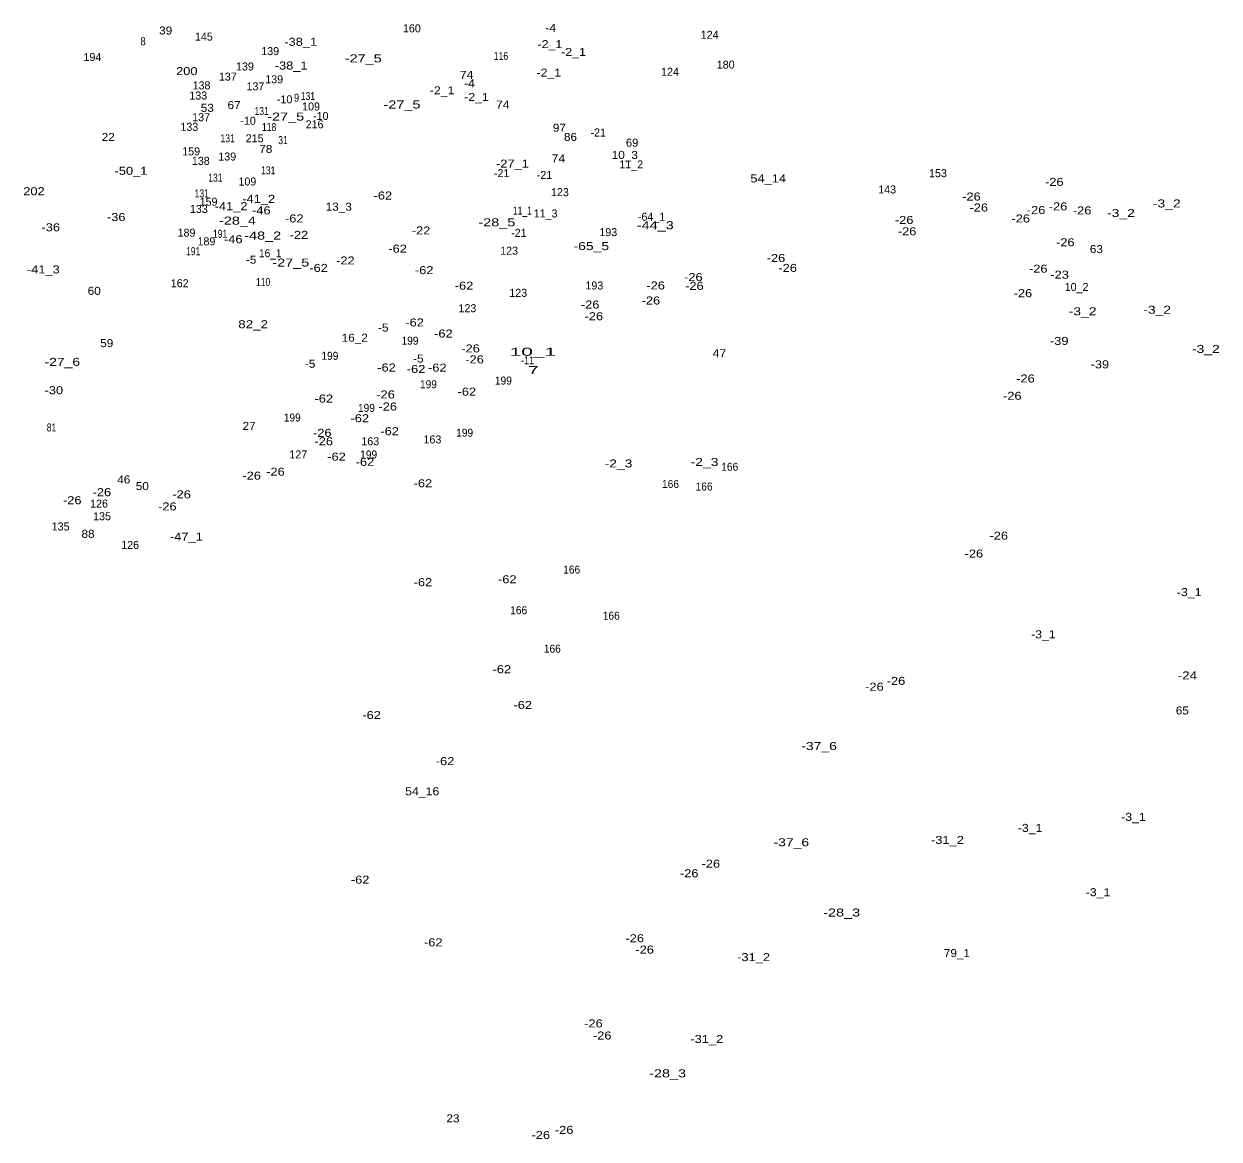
# Model space of a CAD drawing. Extents: x -660405 to -657848, y -988475 to -986360.
# Drawn here: x -658944 to -658347, y -987921 to -987364 of the extents above; entities that cross this region are included whole.
import ezdxf
from ezdxf.enums import TextEntityAlignment as Align

# ---------------------------------------------------------------- set-up
doc = ezdxf.new("R2010")
doc.units = 0
doc.header["$LTSCALE"] = 1.6
doc.layers.add('24', color=7, linetype='Continuous')

msp = doc.modelspace()

# ---------------------------------------------------------------- texts
at = {"layer": '24'}
for s, p in [('160', (-658750.03, -987368.03)), ('145', (-658853.98, -987372.15)), ('124', (-658601.199, -987371.25)), ('139', (-658820.831, -987379.41)), ('194', (-658909.69, -987382.36)), ('180', (-658593.16, -987386.17)), ('137', (-658842.01, -987392.14)), ('139', (-658833.451, -987387.08)), ('124', (-658621.02, -987389.73)), ('138', (-658855.16, -987396.55)), ('137', (-658828.211, -987396.99)), ('139', (-658818.821, -987393.49)), ('133', (-658856.77, -987401.59)), ('-10', (-658813.62, -987403.5)), ('109', (-658800.41, -987407.06)), ('137', (-658855.351, -987412.44)), ('-10', (-658831.88, -987414.2)), ('216', (-658798.64, -987415.96)), ('-10', (-658795.541, -987411.8)), ('133', (-658861.24, -987417.23)), ('-21', (-658656.88, -987420.07)), ('215', (-658828.62, -987422.97)), ('159', (-658860.331, -987429.49)), ('139', (-658842.311, -987432.06)), ('138', (-658855.53, -987434.22)), ('11_2', (-658640.37, -987435.98)), ('109', (-658832.221, -987444.54)), ('-21', (-658705.14, -987440.37)), ('-21', (-658683.75, -987441.28)), ('153', (-658487.079, -987440.38)), ('123', (-658676.02, -987449.86)), ('143', (-658512.49, -987448.53)), ('159', (-658851.64, -987454.63)), ('133', (-658856.49, -987458.27)), ('11_3', (-658683.19, -987460.49)), ('-64_1', (-658630.216, -987462.15)), ('193', (-658651.851, -987469.83)), ('189', (-658862.65, -987470.11)), ('189', (-658852.691, -987474.45)), ('-21', (-658696.551, -987470.18)), ('123', (-658701.429, -987479.12)), ('162', (-658866.061, -987495.35)), ('193', (-658658.821, -987496.48)), ('10_2', (-658417.803, -987497.19)), ('123', (-658696.86, -987500.15)), ('123', (-658722.27, -987507.83)), ('163', (-658770.831, -987574.3)), ('163', (-658739.76, -987573.38)), ('127', (-658806.77, -987580.86)), ('126', (-658906.37, -987605.41)), ('135', (-658904.86, -987611.74)), ('135', (-658925.559, -987616.86)), ('126', (-658890.831, -987626.07))]:
    msp.add_text(s, height=4, dxfattribs=at).set_placement(p, align=Align.CENTER)
for s, width, p in [('-4', 1.15, (-658680.64, -987367.83)), ('39', 1.1, (-658873.07, -987369.12)), ('8', 0.9, (-658884.37, -987374.5)), ('-38_1', 1.2, (-658805.579, -987374.77)), ('-2_1', 1.15, (-658681.03, -987375.94)), ('-2_1', 1.15, (-658669.22, -987379.82)), ('-27_5', 1.35, (-658774.34, -987383.04)), ('116', 0.8, (-658705.5, -987381.85)), ('200', 1.2, (-658862.51, -987389.42)), ('-38_1', 1.2, (-658810.34, -987386.61)), ('74', 1.15, (-658722.67, -987391.28)), ('-2_1', 1.15, (-658681.579, -987390.15)), ('-4', 1.15, (-658721.22, -987395.51)), ('9', 0.85, (-658807.64, -987402.7)), ('131', 0.8, (-658801.97, -987401.85)), ('-2_1', 1.15, (-658734.9, -987399.01)), ('-2_1', 1.15, (-658717.74, -987402.33)), ('53', 1.1, (-658852.28, -987407.74)), ('67', 1.1, (-658838.88, -987406.38)), ('131', 0.8, (-658825.09, -987409.34)), ('-27_5', 1.35, (-658754.96, -987406.08)), ('74', 1.15, (-658704.57, -987406.09)), ('-27_5', 1.35, (-658813.09, -987412.12)), ('118', 0.8, (-658821.37, -987417.32)), ('97', 1.1, (-658676.29, -987417.67)), ('22', 1.1, (-658901.77, -987422.32)), ('131', 0.8, (-658842.09, -987422.97)), ('31', 0.8, (-658814.419, -987423.86)), ('86', 1.1, (-658670.76, -987422.28)), ('69', 1.05, (-658639.95, -987425.17)), ('78', 1.1, (-658823.01, -987428.29)), ('74', 1.15, (-658676.79, -987432.97)), ('10_3', 1.1, (-658643.6, -987431.27)), ('-50_1', 1.2, (-658890.419, -987439.2)), ('131', 0.8, (-658821.8, -987438.97)), ('-27_1', 1.2, (-658699.76, -987435.6)), ('131', 0.8, (-658848.22, -987442.62)), ('54_14', 1.2, (-658571.941, -987443.01)), ('-26', 1.2, (-658428.92, -987444.73)), ('202', 1.2, (-658938.89, -987449.39)), ('131', 0.8, (-658855.07, -987450.49)), ('-62', 1.2, (-658764.53, -987451.54)), ('-41_2', 1.2, (-658840.37, -987456.86)), ('-41_2', 1.2, (-658826.569, -987453.2)), ('13_3', 1.1, (-658786.58, -987457.12)), ('-26', 1.2, (-658470.34, -987452.05)), ('-26', 1.2, (-658466.69, -987457.53)), ('-26', 1.2, (-658427.09, -987456.98)), ('-3_2', 1.3, (-658372.74, -987455.5)), ('-36', 1.2, (-658897.79, -987462.29)), ('-46', 1.2, (-658825.26, -987458.96)), ('-62', 1.2, (-658808.8, -987462.98)), ('11_1', 0.8, (-658694.79, -987459.06)), ('-26', 1.2, (-658503.98, -987463.75)), ('-26', 1.2, (-658445.74, -987463.02)), ('-26', 1.2, (-658438.06, -987458.81)), ('-26', 1.2, (-658415.03, -987458.99)), ('-3_2', 1.3, (-658395.62, -987460.29)), ('-36', 1.2, (-658930.51, -987467.41)), ('-28_4', 1.35, (-658837.18, -987464.08)), ('-22', 1.2, (-658745.42, -987468.99)), ('-28_5', 1.35, (-658707.549, -987464.93)), ('-44_3', 1.35, (-658628.37, -987466.38)), ('-26', 1.2, (-658502.52, -987469.42)), ('191', 0.8, (-658845.861, -987470.66)), ('-46', 1.2, (-658839.28, -987473.36)), ('-48_2', 1.35, (-658824.57, -987471.53)), ('-22', 1.2, (-658806.47, -987471.19)), ('-26', 1.2, (-658423.44, -987474.9)), ('191', 0.8, (-658859.331, -987479.34)), ('16_1', 0.95, (-658820.79, -987480.38)), ('-62', 1.2, (-658757.15, -987478.1)), ('-65_5', 1.3, (-658660.34, -987476.81)), ('63', 1.1, (-658407.92, -987478.31)), ('-5', 1.1, (-658830.37, -987483.58)), ('-27_5', 1.35, (-658810.53, -987485.02)), ('-62', 1.2, (-658796.63, -987487.7)), ('-22', 1.2, (-658783.26, -987483.99)), ('-26', 1.2, (-658568.05, -987482.76)), ('-26', 1.2, (-658562.2, -987487.7)), ('-41_3', 1.2, (-658934.23, -987488.46)), ('-62', 1.2, (-658743.86, -987488.81)), ('-26', 1.2, (-658609.36, -987492.27)), ('-26', 1.2, (-658436.97, -987488.07)), ('-23', 1.2, (-658426.3, -987491.07)), ('60', 1.1, (-658908.791, -987499.17)), ('110', 0.8, (-658824.39, -987494.78)), ('-62', 1.2, (-658723.94, -987496.56)), ('-26', 1.2, (-658628.19, -987496.48)), ('-26', 1.2, (-658608.81, -987496.66)), ('-26', 1.2, (-658630.56, -987503.98)), ('-26', 1.2, (-658444.64, -987500.32)), ('-26', 1.2, (-658660.91, -987505.99)), ('-3_2', 1.3, (-658414.809, -987509.38)), ('-3_2', 1.3, (-658377.54, -987508.59)), ('82_2', 1.25, (-658829.35, -987515.83)), ('-5', 1.1, (-658764.32, -987517.5)), ('-62', 1.2, (-658748.66, -987514.94)), ('-26', 1.2, (-658659.08, -987511.84)), ('16_2', 1.1, (-658778.559, -987522.58)), ('-62', 1.2, (-658734.27, -987520.48)), ('59', 1.1, (-658902.53, -987525.27)), ('199', 0.95, (-658750.95, -987524.05)), ('-26', 1.2, (-658720.69, -987527.91)), ('10_1', 1.95, (-658689.531, -987529.58)), ('-39', 1.2, (-658426.48, -987524.17)), ('-3_2', 1.3, (-658353.189, -987528.16)), ('-27_6', 1.3, (-658924.721, -987534.63)), ('199', 0.95, (-658790.99, -987531.61)), ('-5', 1.1, (-658746.8, -987533)), ('-26', 1.2, (-658718.68, -987533.39)), ('-11', 0.85, (-658692.211, -987533.87)), ('47', 1.15, (-658596.28, -987530.29)), ('-5', 1.1, (-658800.85, -987535.59)), ('-62', 1.2, (-658762.68, -987537.45)), ('-62', 1.2, (-658747.92, -987538.19)), ('-62', 1.2, (-658737.31, -987537.52)), ('7', 1.8, (-658689.276, -987538.68)), ('-39', 1.2, (-658406.19, -987535.88)), ('199', 0.95, (-658741.73, -987545.82)), ('199', 0.95, (-658704.28, -987543.98)), ('-26', 1.2, (-658443.36, -987542.93)), ('-30', 1.2, (-658928.96, -987548.79)), ('-62', 1.2, (-658794.04, -987552.96)), ('-26', 1.2, (-658763.19, -987550.89)), ('-62', 1.2, (-658722.55, -987549.52)), ('-26', 1.2, (-658449.94, -987551.59)), ('199', 0.95, (-658772.72, -987557.63)), ('-26', 1.2, (-658762.09, -987556.93)), ('199', 0.95, (-658809.8, -987562.43)), ('-62', 1.2, (-658776.05, -987562.79)), ('81', 0.8, (-658930.13, -987567.41)), ('27', 1.1, (-658831.39, -987566.63)), ('-26', 1.2, (-658794.81, -987570.09)), ('-62', 1.2, (-658761.11, -987569.25)), ('199', 0.95, (-658723.65, -987570)), ('-26', 1.2, (-658794.08, -987574.3)), ('-62', 1.2, (-658787.68, -987581.98)), ('199', 0.95, (-658771.62, -987580.89)), ('-62', 1.2, (-658773.47, -987584.56)), ('-2_3', 1.3, (-658646.75, -987585.38)), ('-2_3', 1.3, (-658603.77, -987584.64)), ('166', 0.95, (-658591.15, -987587.03)), ('46', 1.1, (-658893.99, -987593.37)), ('-26', 1.2, (-658830.09, -987591.49)), ('-26', 1.2, (-658818.21, -987589.48)), ('-62', 1.2, (-658744.51, -987595.27)), ('-26', 1.2, (-658904.95, -987599.72)), ('50', 1.1, (-658884.76, -987596.67)), ('-26', 1.2, (-658865.1, -987600.81)), ('166', 0.95, (-658620.76, -987595.62)), ('166', 0.95, (-658603.95, -987596.9)), ('-26', 1.2, (-658919.76, -987603.74)), ('-26', 1.2, (-658872.23, -987606.85)), ('88', 1.1, (-658911.87, -987620.52)), ('-47_1', 1.2, (-658862.7, -987621.94)), ('-26', 1.2, (-658456.71, -987621.44)), ('-26', 1.2, (-658469.14, -987630.4)), ('166', 0.95, (-658670.12, -987638.39)), ('-62', 1.2, (-658744.51, -987644.68)), ('-62', 1.2, (-658702.33, -987643.23)), ('-3_1', 1.15, (-658361.53, -987649.65)), ('166', 0.95, (-658696.63, -987658.69)), ('166', 0.95, (-658650.38, -987661.43)), ('-3_1', 1.15, (-658434.39, -987670.74)), ('166', 0.95, (-658679.81, -987677.89)), ('-62', 1.2, (-658705.08, -987688.14)), ('-26', 1.2, (-658508.07, -987693.96)), ('-24', 1.25, (-658362.41, -987691.27)), ('-26', 1.2, (-658518.86, -987696.89)), ('-62', 1.2, (-658694.6, -987706.02)), ('65', 1.1, (-658364.95, -987708.76)), ('-62', 1.2, (-658770.15, -987711.03)), ('-37_6', 1.3, (-658546.5, -987726.52)), ('-62', 1.2, (-658733.44, -987734.06)), ('54_16', 1.15, (-658744.85, -987749.13)), ('-3_1', 1.15, (-658389.37, -987761.9)), ('-3_1', 1.15, (-658441.03, -987767.41)), ('-31_2', 1.2, (-658482.35, -987773.44)), ('-37_6', 1.3, (-658560.39, -987774.59)), ('-26', 1.2, (-658600.63, -987785.29)), ('-26', 1.2, (-658611.42, -987790.05)), ('-62', 1.2, (-658775.87, -987793.27)), ('-3_1', 1.15, (-658407.079, -987799.52)), ('-28_3', 1.35, (-658535.199, -987809.68)), ('-62', 1.2, (-658739.34, -987824.59)), ('-26', 1.2, (-658638.62, -987822.53)), ('-26', 1.2, (-658633.68, -987828.2)), ('-31_2', 1.2, (-658579.23, -987831.95)), ('79_1', 1.1, (-658477.601, -987829.94)), ('-26', 1.2, (-658659.27, -987865.08)), ('-26', 1.2, (-658654.89, -987871.11)), ('-31_2', 1.2, (-658602.63, -987872.84)), ('-28_3', 1.35, (-658622.209, -987890.01)), ('23', 1.1, (-658729.49, -987912.48)), ('-26', 1.2, (-658685.6, -987920.79)), ('-26', 1.2, (-658673.9, -987918.23))]:
    msp.add_text(s, height=4, dxfattribs=dict(at, width=width)).set_placement(p, align=Align.CENTER)

doc.saveas('drawing.dxf')
